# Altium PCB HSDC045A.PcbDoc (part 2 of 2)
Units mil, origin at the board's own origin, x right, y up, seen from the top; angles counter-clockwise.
Board outline 3400 x 2200 mil, 4 copper layers (Top Layer, GND, Power, Bottom Layer), stack 60.6 mil thick; 158 components, 100 nets, 469 pads, 343 vias.
Unrouted connection lines stored in the file: 20.
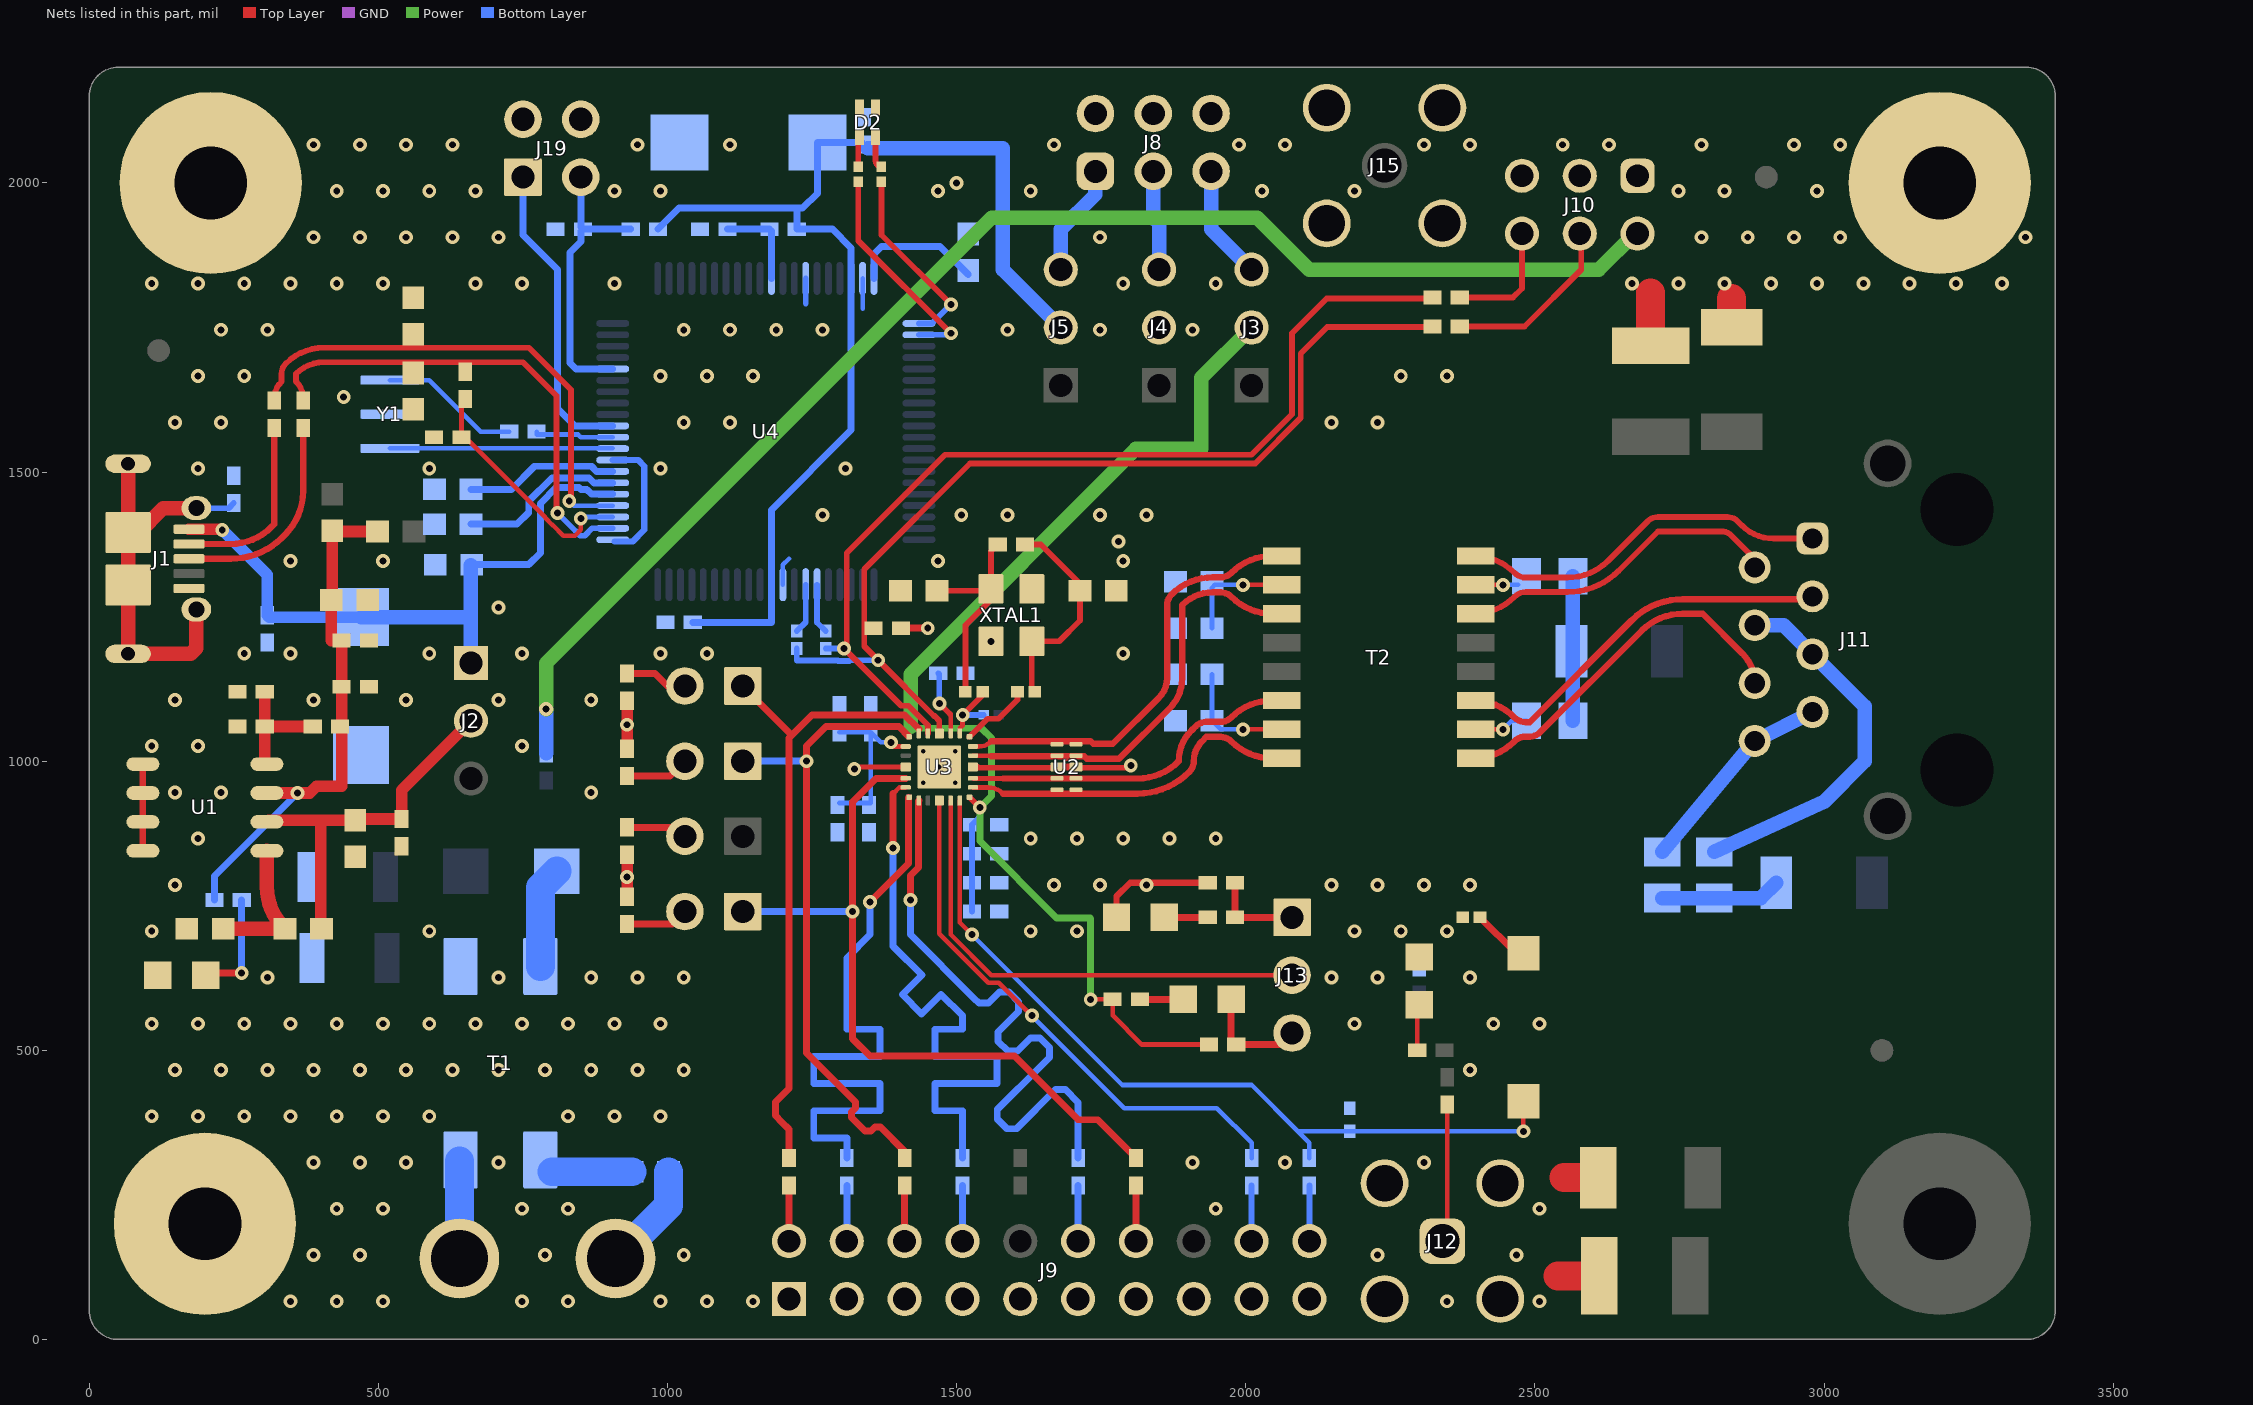
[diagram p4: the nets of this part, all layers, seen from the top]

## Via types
v1: diameter 24, hole 12, Top Layer to Bottom Layer, tented both sides, 337 vias
v2: diameter 19.68, hole 7.87, Top Layer to Bottom Layer, 5 vias
v3: diameter 24, hole 12, Top Layer to Bottom Layer, tented bottom, 1 vias

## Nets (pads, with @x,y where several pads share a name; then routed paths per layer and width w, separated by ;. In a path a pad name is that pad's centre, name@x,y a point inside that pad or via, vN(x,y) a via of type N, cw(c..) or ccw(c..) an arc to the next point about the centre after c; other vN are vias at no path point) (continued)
GND: C1.2 C2.1 C3.2 C4.2 C5.2 C6.2 C7.2 C8.2 C9.2 C10.2 C11.2 C12.2 C13.2 C14.2 C15.2 C16.2 C17.2 C18.2 C19.2 C20.2 C21.2 C22.2 C23.1 C26.2 C27.1 C28.1 C29.2 C30.1 C31.2 C32.2 C33.1 C34.2 C35.2 C36.1 C37.1 C38.1 C39.1 C40.1 D2.3 D2.4 H1.1 H2.1 H3.1 J1.5 J8.2 J8.4 J8.6 J9.1 J9.3 J9.5 J9.7 J9.9 J9.11 J9.13 J9.15 J9.17 J9.19 J10.1 J10.3 J10.5 J12.2 J12.3 J12.4 J12.5 J15.2 J15.3 J15.4 J15.5 J19.2 J19.4 LD1.2 LD3.2 LD4.2 R5.1 R6.1 R7.2 R21.2 R22.1 R31.1 R34.2 R35.2 R36.2 R51.2 T1.3 U1.5 U1.6 U1.7 U1.8 U2.3@1673.56,990 U2.8@1706.44,990 U3.9 U3.21 U3.25 U4.14 U4.19 U4.49 U4.61 U4.68 XTAL1.2 XTAL1.4 Y1.2 | length 1383.2
  Top Layer w8: v1(1322.98,986.69) 1319.73,986.69 1316.42,990 U3.21@1411.93,990
  Top Layer w10: U3.9@1528.07,990 1536.58,990 1538.08,988.5 1673.56,988.5 U2.3@1673.56,989.76 ; U2.8@1706.44,990 1706.44,988.5 1798.5,988.5 1801.09,991.09 v1(1801.09,992.5)
  Top Layer w11: U1.8@92.72,845 U1.7@92.72,895 U1.6@92.72,945 U1.5@92.72,995 ; LD4.2@1776.38,730 1776.38,766.38 1800,790 R31.1@1934.09,790
  Top Layer w12: U2.3@1673.56,990 1673.56,989.76 1706.19,989.76 U2.8@1706.44,990
  Top Layer w50: 2540,110 C27.1@2611.26,110 ; 2550,280 R35.2@2609.45,280 ; C28.1@2700,1718.74 2700,1810 ; R34.2@2840,1750.55 2840,1800
  GND w10: v1@1800,991.41 v1(1801.09,992.5)
  Bottom Layer w8: U4.49@1199.53,1305.24 1199.53,1339.53 1210,1350 ; 1337.32,1782.68 U4.19@1337.32,1834.76
  Bottom Layer w10: 1238.9,1791.57 U4.14@1238.9,1834.76
  Bottom Layer w11: U4.68@905.24,1520.79 949.21,1520.79 960,1510 960,1400 940,1380 U4.61@908.23,1380
  other v1: 348,66 428,66 508,66 748,66 828,66 988,66 1068,66 1148,66 2348,66 2508,66 388,146 468,146 788,146 1028,146 2228,146 2468,146 428,226 508,226 748,226 828,226 1948,226 2508,226 388,306 468,306 548,306 708,306 1908,306 2068,306 2308,306 108,386 188,386 268,386 348,386 428,386 508,386 588,386 828,386 908,386 988,386 148,466 228,466 308,466 388,466 468,466 548,466 628,466 708,466 788,466 868,466 948,466 1028,466 2388,466 108,546 188,546 268,546 348,546 428,546 508,546 588,546 668,546 748,546 828,546 908,546 988,546 2188,546 2428,546 2508,546 308,626 708,626 868,626 948,626 1028,626 2148,626 2228,626 2388,626 108,706 588,706 1628,706 1708,706 2188,706 2268,706 2348,706 148,786 1668,786 1748,786 1828,786 2148,786 2228,786 2308,786 2388,786 188,866 1628,866 1708,866 1788,866 1868,866 1948,866 148,946 228,946 868,946 108,1026 188,1026 748,1026 148,1106 388,1106 548,1106 708,1106 868,1106 268,1186 348,1186 588,1186 748,1186 988,1186 1068,1186 1788,1186 1559.13,1207.31 708,1266 348,1346 508,1346 1468,1346 1788,1346 1780,1380 1268,1426 1508,1426 1588,1426 1748,1426 1828,1426 188,1506 588,1506 988,1506 1308,1506 148,1586 228,1586 1028,1586 1108,1586 2148,1586 2228,1586 440,1630 188,1666 268,1666 988,1666 1068,1666 1148,1666 2268,1666 2348,1666 228,1746 308,1746 1028,1746 1108,1746 1188,1746 1268,1746 1588,1746 1748,1746 1908,1746 108,1826 188,1826 268,1826 348,1826 428,1826 508,1826 668,1826 748,1826 908,1826 1788,1826 1948,1826 2668,1826 2748,1826 2828,1826 2908,1826 2988,1826 3068,1826 3148,1826 3228,1826 3308,1826 388,1906 468,1906 548,1906 628,1906 708,1906 1748,1906 2788,1906 2868,1906 2948,1906 3028,1906 3348,1906 428,1986 508,1986 588,1986 668,1986 908,1986 988,1986 1468,1986 1628,1986 2028,1986 2188,1986 2748,1986 2828,1986 2988,1986 1500,2000 388,2066 468,2066 548,2066 628,2066 948,2066 1108,2066 1668,2066 1988,2066 2068,2066 2308,2066 2388,2066 2548,2066 2628,2066 2788,2066 2948,2066 3028,2066
  other v2: 1442.44,962.44 1497.56,962.44 1470,990 1442.44,1017.56 1497.56,1017.56
LED_0: J13.2 U3.4 | length 851.1
  Top Layer w8: U3.4@1489.69,931.93 1489.69,700.31 1560,630 J13.2@2080,630
MCU_VCC: C35.1 C36.2 C37.2 J5.2 R49.1 R52.1 U4.18 U4.50 | length 2032.6
  Bottom Layer w12: R49.1@983.62,1920 1020,1956.38 1233.62,1956.38 1259.09,1981.85 C35.1@1259.09,2070 C36.2@1336.38,2070 ; C37.2@1043.62,1240 1043.78,1240.16 1179.84,1240.16 U4.50@1179.84,1305.24 1179.84,1434.57 1317.64,1572.36 U4.18@1317.64,1834.76 1317.64,1887.64 1285.28,1920 R52.1@1223.62,1920 1223.62,1952.76
  Bottom Layer w25: C36.2@1346.38,2060 1580,2060 1580,1850 J5.2@1680,1750
MCU_VCC_EXT: J5.3 J8.1 | length 194.9
  Bottom Layer w25: J5.3@1680,1850 1680,1920 1740,1980 J8.1@1740,2020
MDC: R18.1 R46.1 U3.16 | length 1686.8
  Top Layer w10: v1(1304.96,1195.04) v1(1304.96,1195.04) ; U3.16@1450.31,1048.07 1450.57,1048.32 1450.57,1062.06 1416.63,1096 1404,1096 1310,1190 1310,1360 1480,1530 2010,1530 2080,1600 2080,1740 2140,1800 2320.79,1800 R18.1@2322.6,1801.81
  Bottom Layer w10: R46.1@1273.5,1195.04 v1(1304.96,1195.04)
MDC_EXT: J10.6 R18.2 | length 209
  Top Layer w10: R18.2@2369.84,1801.81 2461.81,1801.81 2477.5,1817.5 J10.6@2477.5,1912.31
MDC_OB: R46.2 U4.46 | length 86.5
  Bottom Layer w10: U4.46@1258.58,1305.24 1258.58,1239.88 R46.2@1273.5,1224.96
MDIO: R19.1 R20.1 R47.1 U3.15 | length 1722.5
  Top Layer w10: U3.15@1470,1048.07 1470,1070 1462,1078 1460.89,1078 v1(1364.32,1174.57) 1340,1198.89 1340,1331.73 1523.27,1515 2016.21,1515 2095,1593.79 2095,1705 2140.81,1750.81 2321.6,1750.81 R19.1@2322.6,1751.81
  Bottom Layer w10: R47.1@1223.5,1195.04 1223.5,1174.57 1224.06,1174.02 1294.32,1174.02 1295.3,1173.04 1314.07,1173.04 1315.6,1174.57 v1(1364.32,1174.57)
MDIO_EXT: J10.4 R19.2 | length 314.2
  Top Layer w10: R19.2@2369.84,1751.81 2481.81,1751.81 2580,1850 2580,1909.81 J10.4@2577.5,1912.31
MDIO_OB: R47.2 U4.47 | length 86.7
  Bottom Layer w10: R47.2@1223.5,1224.96 1238.9,1240.35 U4.47@1238.9,1305.24
MSP_XIN2: U4.69 Y1.3 | length 384.8
  Bottom Layer w8: Y1.3@520,1540.94 U4.69@904.76,1540.94
MSP_XOUT2: R48.2 U4.70 | length 138.8
  Bottom Layer w8: R48.2@773.62,1570 773.62,1564.84 845.16,1564.84 850,1560 905.08,1560 U4.70@905.24,1560.16
NetC3_1: C3.1 C4.1 J2.2 R2.2 U1.2 | length 638.9
  Top Layer w20: U1.2@310.16,897.87 400,897.87 ; R2.2@401.5,710 400,711.5 400,897.87 ; J2.2@660,1070 540,950 C3.1@540,900 462.13,900 C4.1@460,897.87 400,897.87
NetC5_1: C5.1 C6.1 C7.1 L1.1 R1.1 R3.2 R4.2 U1.3 | length 898.7
  Top Layer w20: U1.3@307.28,945 v1(360,945) 381.18,945 392.95,956.77 436.38,956.77 C5.1@436.38,1128.7 C6.1@436.38,1208.7 ; 418.5,1208.7 C7.1@418.5,1278.7 ; C7.1@420,1278.7 L1.1@420,1397.22 ; L1.1@420,1398.5 L1.1@420,1397.22 ; R1.1@498.5,1397.22 L1.1@420,1397.22
  Bottom Layer w12: R4.2@216.38,760 216.38,801.38 v1(360,945)
NetC8_1: C8.1 R3.1 R6.2 U1.4 | length 209.3
  Top Layer w20: C8.1@303.62,1120 R6.2@303.62,1060 ; U1.4@307.28,995 303.62,998.66 R6.2@303.62,1060 ; R3.1@386.38,1060 R6.2@303.62,1060
NetC11_1: C11.1 C12.1 T2.2 | length 177.8
  Top Layer w8: v1(1995,1305) T2.2@2047.36,1305
  Bottom Layer w8: C11.1@1941.5,1230.06 1941.5,1299.91 1946.58,1305 v1(1995,1305)
NetC21_1: C21.1 C22.1 T2.7 | length 192.1
  Top Layer w8: v1(1995,1055) T2.7@2047.36,1055
  Bottom Layer w8: C22.1@1941.5,1150.03 C21.1@1941.5,1070 1956.5,1055 v1(1995,1055)
NetC24_1: C24.1 R23.1 R24.1 | length 250
  Bottom Layer w25: R23.1@2565.59,1070 R24.1@2565.59,1320
NetC25_1: C25.1 R25.1 R26.1 | length 208.4
  Bottom Layer w25: R26.1@2720,763.31 R25.1@2810,763.31 2890.63,763.31 C25.1@2917.32,790
NetC26_1: C26.1 R33.1 R37.2 XTAL1.3 | length 367.1
  Top Layer w10: R37.2@1618.19,1374.72 1645.28,1374.72 1713.07,1306.93 C26.1@1713.07,1294.66 1713.07,1243.07 1677.31,1207.31 XTAL1.3@1630,1207.31 R33.1@1630,1124.96
NetC29_1: C29.1 R37.1 R38.1 XTAL1.1 | length 349
  Top Layer w10: C29.1@1466.06,1294.72 XTAL1.1@1555.99,1294.72 ; R38.1@1515.04,1120 1515.04,1234.96 XTAL1.1@1559.13,1279.05 ; XTAL1.1@1559.13,1297.87 1559.13,1362.91 R37.1@1570.94,1374.72
NetC31_1: C31.1 U4.67 | length 265.5
  Bottom Layer w12: C31.1@660,1470 730,1470 770,1510 868.4,1510 877.3,1501.1 U4.67@905.24,1501.1
NetC32_1: C32.1 U4.20 | length 230.7
  Bottom Layer w12: U4.20@1357.01,1834.76 1357.01,1877.01 1370,1890 1471.5,1890 C32.1@1520,1841.5
NetC34_1: C34.1 U4.66 | length 293.7
  Bottom Layer w12: C34.1@660,1410 740,1410 760,1430 760,1450.04 799.96,1490 864.36,1490 872.94,1481.42 U4.66@905.24,1481.42
NetC38_2: C38.2 R52.2 U4.11 | length 154.5
  Bottom Layer w12: C38.2@1103.62,1920 R52.2@1176.38,1920 ; U4.11@1179.84,1834.76 R52.2@1179.84,1916.54
NetD1_2: D1.2 T1.4 | length 176.8
  Bottom Layer w50: T1.4@780,645.13 780,781.26 D1.2@808.74,810
NetD2_1: D2.1 R45.1 | length 48.8
  Top Layer w10: R45.1@1329.84,2028.3 D2.1@1329.84,2077.12
NetD2_2: D2.2 R44.1 | length 57
  Top Layer w10: D2.2@1359.84,2079.56 1359.84,2038.3 ccw(c1369.84,2038.3) R44.1@1369.84,2028.3
NetF1_1: F1.1 J6.1 | length 187.9
  Bottom Layer w50: J6.1@910,140 1001.5,231.5 F1.1@1001.5,290
NetF1_2: F1.2 T1.1 | length 138
  Bottom Layer w50: T1.1@800.49,290 F1.2@938.5,290
NetJ1_6: J1.6 J1.7 J1.8 J1.9 J1.10 J1.11 R7.1 | length 722.1
  Top Layer w25: J1.10@67.09,1514.37 J1.9@67.09,1395.28 ; J1.6@185.2,1262.4 185.2,1195.2 175.63,1185.63 J1.7@67.09,1185.63 J1.8@67.09,1304.72 J1.9@67.09,1395.28 ; J1.11@185.2,1437.6 127.6,1437.6 85.28,1395.28 J1.9@67.09,1395.28
  Bottom Layer w10: J1.11@185.2,1437.6 241.22,1437.6 R7.1@250,1446.38
NetJ7_1: J7.1 T1.2 | length 158.3
  Bottom Layer w50: J7.1@640,150 T1.2@640,308.27
NetJ11_4: J11.4 J11.5 R25.2 | length 650.8
  Bottom Layer w25: R25.2@2810,843.31 3000,930 3070,1000 3070,1095 J11.5@2980,1185 2930,1235 J11.4@2880,1235
NetJ11_7: J11.7 J11.8 R26.2 | length 361.5
  Bottom Layer w25: R26.2@2720,843.31 J11.8@2880,1035 J11.7@2980,1085
NetJ12_1: J12.1 R27.2 | length 239.8
  Top Layer w8: J12.1@2340,170 2348.19,178.19 R27.2@2348.19,406.38
NetJ13_1: J13.1 R31.2 R32.1 | length 158.7
  Top Layer w12: R31.2@1981.34,790 R32.1@1981.34,730 J13.1@2080,730
NetJ13_3: J13.3 LD2.2 R29.1 | length 186.6
  Top Layer w12: LD2.2@1974.67,588.22 1974.67,518.96 R29.1@1983.62,510 2060,510 J13.3@2080,530
NetJ14_2: J14.2 R39.1 | length 109
  Top Layer w12: R39.1@930,718.38 1008.38,718.38 J14.2@1030,740
NetJ16_2: J16.2 R40.1 | length 109
  Top Layer w12: R40.1@930,1151.62 978.38,1151.62 1000,1130 J16.2@1030,1130
NetJ17_2: J17.2 R42.1 | length 110.6
  Top Layer w12: R42.1@930,974.38 1004.38,974.38 J17.2@1030,1000
NetJ18_2: J18.2 R43.1 | length 106.5
  Top Layer w12: R43.1@930,885.62 1014.38,885.62 J18.2@1030,870
NetLD1_1: LD1.1 R4.1 | length 190.2
  Top Layer w12: LD1.1@201.34,630 204.96,633.62 v1(263.62,633.62)
  Bottom Layer w12: v1(263.62,633.62) R4.1@263.62,760
NetLD2_1: LD2.1 R28.1 | length 75
  Top Layer w12: R28.1@1816.95,588.22 LD2.1@1891.99,588.22
NetLD3_1: LD3.1 R30.2 | length 79.6
  Top Layer w8: R30.2@2296.38,500 2296.38,569.92 cw(c2308.74,569.92) LD3.1@2300,578.66
NetLD4_1: LD4.1 R32.2 | length 75
  Top Layer w12: LD4.1@1859.06,730 R32.2@1934.09,730
NetR2_1: R2.1 R5.2 U1.1 | length 250.6
  Top Layer w25: R5.2@231.5,710 R2.1@338.5,710 336.57,711.93 cw(c407.28,782.64) 307.28,782.64 U1.1@307.28,845
NetR22_2: R22.2 S1.1 | length 87.7
  Top Layer w12: R22.2@2404.96,730 S1.1@2467.01,667.95
NetR23_2: R23.2 T2.10 | length 99.2
  Top Layer w8: T2.10@2392.64,1055 v1(2445,1055)
  Bottom Layer w8: v1(2445,1055) 2460,1070 R23.2@2485.59,1070
NetR24_2: R24.2 T2.15 | length 78
  Top Layer w8: T2.15@2392.64,1305 v1(2445,1305)
  Bottom Layer w8: v1(2445,1305) R24.2@2470.59,1305
NetR48_1: R48.1 Y1.1 | length 243.3
  Bottom Layer w8: Y1.1@520,1659.06 587.6,1659.06 676.65,1570 R48.1@726.38,1570
P1.0: R44.2 U4.21 | length 331
  Top Layer w10: R44.2@1369.84,2002.31 1369.84,1910.16 v1(1490,1790)
  Bottom Layer w10: U4.21@1434.76,1757.01 1457.01,1757.01 v1(1490,1790)
P1.1: R45.2 U4.22 | length 385
  Top Layer w10: R45.2@1329.84,2002.31 1329.84,1900.16 v1(1490,1740)
  Bottom Layer w10: U4.22@1434.76,1737.32 1487.32,1737.32 v1(1490,1740)
PWDN: R16.2 U3.3 | length 946.5
  Top Layer w8: U3.3@1470,931.93 1470,701.62 1554.62,617 1573,617 v1(1630,560)
  Bottom Layer w8: v1(1630,560) 1790,400 1950,400 2010,340 R16.2@2010,313.62
PWDN_S: J9.18 R16.1 | length 96.4
  Bottom Layer w10: J9.18@2010,170 R16.1@2010,266.38
RBIAS: R21.1 U3.14 | length 111.5
  Top Layer w8: 1489.44,1080.56 1489.44,1048.31 U3.14@1489.69,1048.07
  Top Layer w10: v1(1470,1100) 1488.44,1081.56
  Bottom Layer w10: R21.1@1468.19,1152.13 1470,1150.32 v1(1470,1100)
RD_N: T2.8 U2.5 U2.6 U3.7 | length 582.2
  Top Layer w8: U3.7@1528.07,954.57 1554.49,954.57 cw(c1554.49,918.49) 1580,944
  Top Layer w11: 1580,944 1812.58,944 ccw(c1812.58,1070) 1901.67,980.9 1902.38,981.62 ccw(c1884,1000) 1910,1000 cw(c1959.07,1000) 1924.37,1034.7 1931.67,1042 1956.36,1042 cw(c1956.36,1015.67) 1974.97,1034.29 ccw(c2045.69,1105) 2045.69,1005 T2.8@2047.36,1005
RD_P: T2.6 U2.4 U2.7 U3.8 | length 579
  Top Layer w8: U3.8@1528.39,970 1580,970
  Top Layer w11: 1580,970 1812.58,970 ccw(c1812.58,1070) 1883.29,999.29 1884,1000 cw(c1959.07,1000) 1905.99,1053.08 1913.29,1060.38 cw(c1931.67,1042) 1931.67,1068 1956.36,1068 ccw(c1956.36,1094.33) 1974.97,1075.71 cw(c2045.69,1005) 2045.69,1105 T2.6@2047.36,1105
RESET: C23.2 R17.2 S1.2 U3.5 | length 1441.7
  Top Layer w8: U3.5@1505.43,931.93 1505.43,721.09 v1(1526.53,700) ; v1(2480,360) S1.2@2480,412.05
  Bottom Layer w8: v1(1526.53,700) 1786.53,440 2010,440 2090,360 ; R17.2@2110,313.62 2110,340 2090,360 ; v1(2480,360) 2090,360
RESET_S: J9.20 R17.1 | length 96.4
  Bottom Layer w10: J9.20@2110,170 R17.1@2110,266.38
RST/SBWTDIO: C30.2 J19.3 R49.2 U4.76 | length 487.6
  Bottom Layer w12: C30.2@850,1923.62 J19.3@850,2010 ; U4.76@905.24,1678.27 841.73,1678.27 831.65,1688.35 831.65,1880 850,1898.35 850,1916.38 C30.2@853.62,1920 R49.2@936.38,1920
RX_D0: J17.1 R11.2 U3.18 | length 1121.6
  Top Layer w12: R11.2@1410,313.62 1410,325.5 1368.37,367.13 1358.4,367.13 1351.6,360.34 1341.63,360.34 1318.37,383.6 1318.37,393.57 1325.16,400.37 1325.16,410.34 1240,495.5 v1(1240,1000) 1240,1025.98 1274.02,1060 1400,1060 U3.18@1416.85,1043.15
  Bottom Layer w12: J17.1@1130,1000 v1(1240,1000)
RX_D0_S: J9.6 R11.1 | length 96.4
  Top Layer w12: J9.6@1410,170 R11.1@1410,266.38
RX_D1: J16.1 R9.2 U3.17 | length 1110.3
  Top Layer w12: J16.1@1130,1130 1210,1050 ; R9.2@1210,313.62 1210,351.75 1210,363.5 1198.25,375.25 1186.5,387 1186.5,410.5 1198.25,422.25 1210,434 1210,950 1210,1040 1250,1080 1410,1080 U3.17@1434.57,1055.43
RX_D1_S: J9.2 R9.1 | length 96.4
  Top Layer w12: J9.2@1210,170 R9.1@1210,266.38
RX_ER: J14.1 R15.2 U3.22 | length 1283.8
  Top Layer w12: U3.22@1411.93,970.31 1360.78,970.31 1320,929.54 v1(1320,740) 1320,520 1350,490 1600,490 1710,380 1743.62,380 R15.2@1810,313.62
  Bottom Layer w12: J14.1@1130,740 v1(1320,740)
RX_ER_S: J9.14 R15.1 | length 96.4
  Top Layer w12: J9.14@1810,170 R15.1@1810,266.38
TARGET_D_N: C40.2 R53.1 U4.64 | length 867.8
  Top Layer w10: R53.1@320,1623.62 320,1626.69 cw(c362.68,1626.69) 332.5,1656.87 332.5,1670 cw(c357.5,1670) 339.82,1687.68 cw(c405.78,1621.72) 405.78,1715 760.36,1715 833,1642.36 v1@833,1453
  Bottom Layer w8: v1(830,1450) 837.95,1442.05 U4.64@905.24,1442.05
TARGET_D_P: C39.2 R50.2 R54.1 U4.62 | length 853.2
  Top Layer w10: R54.1@370,1623.62 370,1626.69 ccw(c327.32,1626.69) 357.5,1656.87 357.5,1670 cw(c405.78,1621.72) 405.78,1690 750,1690 808,1632 808,1430.99 v1(809.49,1429.49)
  Bottom Layer w10: v1(809.49,1429.49) 809.49,1429.39 840.89,1398 840.99,1398 848.99,1390 856.85,1390 869.53,1402.68 U4.62@905.24,1402.68
  Bottom Layer w11: v1(809.49,1429.49) v1@811.65,1427.34
TARGET_PUR: R50.1 R51.1 U4.63 | length 441.9
  Top Layer w8: R50.1@650,1626.38 643.62,1620 R51.1@643.62,1560 650,1560 788.49,1421.51 788.49,1420.8 800.8,1408.49 801.51,1408.49 820,1390 840,1390 850,1400 v1(850,1420)
  Bottom Layer w8: v1(850,1420) 844.72,1420 842.36,1422.36 U4.63@905.24,1422.36
TD_CH1_N: J11.2 T2.14 | length 567.4
  Top Layer w10: T2.14@2392.64,1255 2393.81,1255 ccw(c2393.81,1355) 2464.53,1284.29 cw(c2484.35,1264.47) 2484.35,1292.5 2556.08,1292.5 ccw(c2556.08,1417.5) 2644.47,1329.11 2712.68,1397.32 2822.32,1397.32 cw(c2822.32,1372.32) 2840,1390 2869.39,1360.61 cw(c2843.79,1335) J11.2@2880,1335
TD_CH1_P: J11.1 T2.16 | length 646.5
  Top Layer w10: T2.16@2392.64,1355 2393.81,1355 cw(c2393.81,1255) 2464.53,1325.71 ccw(c2484.35,1345.53) 2484.35,1317.5 2556.08,1317.5 ccw(c2556.08,1417.5) 2626.79,1346.79 2695,1415 cw(c2712.68,1397.32) 2712.68,1422.32 2832.68,1422.32 cw(c2832.68,1397.32) 2850.36,1415 2857.68,1407.68 ccw(c2912.43,1462.43) 2912.43,1385 J11.1@2980,1385
TD_CH2_N: J11.6 T2.9 | length 644.2
  Top Layer w11: T2.9@2392.64,1005 2393.81,1005 ccw(c2393.81,1105) 2464.53,1034.29 cw(c2484.35,1014.47) 2484.35,1042.5 2491.14,1042.5 ccw(c2491.14,1067.5) 2508.82,1049.82 2684.71,1225.71 cw(c2755.42,1155) 2755.42,1255 2790,1255 2858.79,1186.21 cw(c2807.57,1135) J11.6@2880,1135
TD_CH2_P: J11.3 T2.11 | length 681.4
  Top Layer w11: T2.11@2392.64,1105 2393.81,1105 cw(c2393.81,1005) 2464.53,1075.71 ccw(c2484.35,1095.53) 2484.35,1067.5 2491.14,1067.5 2667.03,1243.39 cw(c2755.42,1155) 2755.42,1280 2967.93,1280 ccw(c2967.93,1297.07) J11.3@2980,1285
TD_N: T2.3 U2.2 U2.9 U3.10 | length 737.8
  Top Layer w8: U3.10@1528.07,1009.69 1556.84,1009.69 cw(c1556.84,1005.21) 1560,1008.37
  Top Layer w11: 1560,1008.37 1687.88,1008.37 1690,1006.26 1692.12,1008.37 1720.76,1008.37 1725.13,1004 1780.77,1004 1868.38,1091.62 ccw(c1816.2,1143.8) 1890,1143.8 1890,1270 cw(c1943.11,1216.89) 1943.11,1292 1956.36,1292 cw(c1956.36,1265.67) 1974.97,1284.29 ccw(c2045.69,1355) 2045.69,1255 T2.3@2047.36,1255
TD_P: T2.1 U2.1 U2.10 U3.11 | length 737
  Top Layer w8: U3.11@1528.07,1025.43 1538.41,1025.43 ccw(c1538.41,1055.96) 1560,1034.37
  Top Layer w11: 1560,1034.37 1731.52,1034.37 1735.9,1030 1770,1030 1850,1110 ccw(c1816.2,1143.8) 1864,1143.8 1864,1270 cw(c1890,1270) 1871.62,1288.38 cw(c1943.11,1216.89) 1943.11,1318 1956.36,1318 ccw(c1956.36,1344.33) 1974.97,1325.71 cw(c2045.69,1255) 2045.69,1355 T2.1@2047.36,1355
TEST/SBWTCK: J19.1 U4.71 | length 532.6
  Bottom Layer w12: J19.1@750,2010 750,1910 810,1850 810,1610 840.16,1579.84 U4.71@905.24,1579.84
TX_D0: R12.2 U3.23 | length 1112.6
  Top Layer w8: 1390,943.82 1400.75,954.57 U3.23@1411.93,954.57
  Top Layer w12: v1(1390,850) 1390,943.82
  Bottom Layer w12: v1(1390,850) 1390,680 1439.85,630.15 1406.1,596.4 1439.33,563.16 1473.09,596.91 1510,560 1510,536.5 1462.27,536.5 1462.27,489.5 1569.97,489.5 1569.97,442.5 1462.27,442.5 1462.27,395.5 1510,395.5 R12.2@1510,313.62
TX_D0_S: J9.8 R12.1 | length 96.4
  Bottom Layer w12: J9.8@1510,170 R12.1@1510,266.38
TX_D1: R10.2 U3.24 | length 1124.8
  Top Layer w12: v1(1350,756.3) 1416.85,823.15 U3.24@1416.85,936.85
  Bottom Layer w12: R10.2@1310,313.62 1310,320 1310,348.5 1252.84,348.5 1252.84,395.5 1310,395.5 1367.16,395.5 1367.16,442.5 1310,442.5 1252.84,442.5 1252.84,489.5 1310,489.5 1367.16,489.5 1367.16,536.5 1310,536.5 1310,560 1310,630 1310,660 1350,700 v1(1350,756.3)
TX_D1_S: J9.4 R10.1 | length 96.4
  Bottom Layer w12: J9.4@1310,170 R10.1@1310,266.38
TX_EN: R14.2 U3.1 | length 1125.1
  Top Layer w12: v1(1420,760) 1420,802.26 1433.85,816.11 1433.85,931.21 U3.1@1434.57,931.93
  Bottom Layer w12: v1(1420,760) 1420,700 1530,590 1538.31,581.69 1554.93,581.69 1573.85,600.62 1590.47,600.62 1607.09,584 1607.09,567.39 1579.85,540.15 1571.76,532.06 1571.76,515.45 1588.38,498.83 1605,498.83 1613.09,506.91 1627.32,521.15 1643.94,521.15 1660.55,504.53 1660.55,487.92 1646.32,473.68 1570.21,397.57 1570.21,380.96 1586.83,364.34 1603.45,364.34 1671.24,432.14 1687.86,432.14 1710,410 R14.2@1710,313.62
TX_EN_S: J9.12 R14.1 | length 96.4
  Bottom Layer w12: J9.12@1710,170 R14.1@1710,266.38
USB_N: J1.2 R53.2 | length 323.9
  Top Layer w11: J1.2@172.4,1375.59 244.17,1375.59 ccw(c244.17,1475.59) 314.88,1404.88 320,1410 R53.2@320,1576.38
USB_P: J1.3 R54.2 | length 371
  Top Layer w11: J1.3@172.4,1350 244.58,1350 ccw(c244.58,1476) 333.67,1386.9 338.38,1391.62 ccw(c262.06,1467.94) 370,1467.94 R54.2@370,1576.38
USB_VBUS: C1.1 C2.2 C33.2 J1.1 J2.1 U4.65 | length 1113.1
  Top Layer w20: J1.1@172.4,1401.18 228.82,1401.18 v1(230,1400)
  Bottom Layer w12: C33.2@661.5,1340 760,1340 780,1360 780,1446 807,1473 847,1473 850,1470 860.32,1470 868.58,1461.73 U4.65@905.24,1461.73
  Bottom Layer w20: v1(230,1400) 307.6,1322.4 C2.2@307.6,1252.44 310.94,1249.09 C1.1@470,1249.09
  Bottom Layer w25: C1.1@470,1249.09 659.09,1249.09 ; J2.1@660,1170 C33.2@660,1338.5
VDDA3P3: C13.1 C14.1 C17.1 C18.1 J3.2 R28.2 R29.2 U3.6 | length 2185.1
  Top Layer w8: v1(1731.78,588.22) R28.2@1769.7,588.22 1769.7,560.3 1820,510 R29.2@1936.38,510
  Top Layer w10: U3.6@1523.15,936.85 v3(1540,920)
  Power w12: 1420.28,1059.72 1423,1057 1543,1057 1560,1040 1560,940 v3(1540,920) 1540,861.65 1672.65,729 1731,729 1731.78,728.22 v1(1731.78,588.22)
  Power w25: 1420.28,1059.72 1420.28,1150.28 1810,1540 1922.94,1540 1922.94,1662.94 J3.2@2010,1750
  Bottom Layer w10: C13.1@1526.38,740 C14.1@1526.38,790 C18.1@1526.38,840 C17.1@1526.38,890 1540,903.62 v3(1540,920)
VDDA3P3_EXT: J3.3 J8.5 | length 199
  Bottom Layer w25: J8.5@1940,2020 1940,1920 J3.3@2010,1850
VDDIO: C15.1 C16.1 C19.1 C20.1 J4.2 R20.2 R39.2 R40.2 R42.2 R43.2 U3.19 | length 512.2
  Top Layer w8: v1(1386.66,1032.68) 1386.66,1025.43 U3.19@1411.93,1025.43
  Top Layer w12: R20.2@1403.62,1230 v1(1450,1230)
  Top Layer w20: R39.2@930,765.62 R43.2@930,838.38 ; R42.2@930,1021.62 R40.2@930,1104.38
  GND w8: v1@1383.44,1035.91 v1(1386.66,1032.68)
  Bottom Layer w8: C15.1@1297.26,927.72 1351.65,927.72 C20.1@1351.65,1050 ; C19.1@1297.26,1050 C20.1@1351.65,1050 ; v1(1386.66,1032.68) 1368.97,1032.68 C20.1@1351.65,1050
  other v1: 930,800 930,1063
VDDIO_EXT: J4.3 J8.3 | length 174.1
  Bottom Layer w25: J8.3@1840,2020 1840,1940 1850,1930 J4.3@1850,1850
VFX: J10.2 R8.1 | length 2425.7
  Power w25: v1(790,1090) 790,1169.73 1560.27,1940 2020,1940 2110,1850 2610,1850 2672.31,1912.31 J10.2@2677.5,1912.31
  Bottom Layer w25: R8.1@790,1013.62 v1(790,1090)
XI: R38.2 R41.2 U3.13 | length 119.4
  Top Layer w8: U3.13@1505.43,1048.07 1505.43,1056.69 1510,1061.26 v1@1510,1079.56
  Top Layer w10: v1@1510,1079.56 v1(1510.44,1080) R38.2@1544.96,1114.52
  Bottom Layer w10: v1(1510.44,1080) R41.2@1547.01,1080
XO: R33.2 U3.12 | length 123.2
  Top Layer w10: U3.12@1522.17,1042.17 1553.5,1073.5 1572.36,1073.5 1605.04,1106.18 R33.2@1605.04,1120
pads on no net: FID1.1 FID2.1 FID3.1 FID4.1 FID5.1 FID6.1 H5.0 H6.0 H7.0 H8.0 J1.4 J9.16 J11. LBL1.0 T2.4 T2.5 T2.12 T2.13 U2.3@1673.56,990 U2.8@1706.44,990 U4.1 U4.2 U4.3 U4.4 U4.5 U4.6 U4.7 U4.8 U4.9 U4.10 U4.12 U4.13 U4.15 U4.16 U4.17 U4.23 U4.24 U4.25 U4.26 U4.27 U4.28 U4.29 U4.30 U4.31 U4.32 U4.33 U4.34 U4.35 U4.36 U4.37 U4.38 U4.39 U4.40 U4.41 U4.42 U4.43 U4.44 U4.45 U4.48 U4.51 U4.52 U4.53 U4.54 U4.55 U4.56 U4.57 U4.58 U4.59 U4.60 U4.72 U4.73 U4.74 U4.75 U4.77 U4.78 U4.79 U4.80

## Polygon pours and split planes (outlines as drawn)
GND on Top Layer "TOP_LAYER_GND_P004" (solid, remove dead copper, pour order 4): 50,2180 3350,2180 3380,2150 3380,1800 2650,1800 2300,1600 2300,1500 2030,1500 2030,820 2430,820 2560,690 2560,20 50,20 20,50 20,2150
EARTH_GND on Top Layer "Top_Earth" (solid, remove dead copper, pour order 11): 3380,1600 2600,1600 2530,1500 2400,1500 2400,900 2730,900 2730,20 3360,20 3380,40
GND on GND "GND_GND_P013" (solid, remove dead copper, pour order 13): 50,2180 3350,2180 3380,2150 3380,1800 2650,1800 2300,1600 2300,1500 2030,1500 2030,820 2430,820 2560,690 2560,20 50,20 20,50 20,2150
EARTH_GND on GND "GND_EARTH_GND" (solid, remove dead copper, pour order 14): 3380,1600 2600,1600 2530,1500 2400,1500 2400,900 2730,900 2730,20 3360,20 3380,40
VDDIO on Power "POWER_VDDIO_P015" (solid, remove dead copper, pour order 15): 50,2180 3350,2180 3380,2150 3380,1800 2650,1800 2300,1600 2300,1500 2030,1500 2030,820 2430,820 2560,690 2560,20 50,20 20,50 20,2150
EARTH_GND on Power "POWER_EARTH_GND_P016" (solid, remove dead copper, pour order 16): 3380,1600 2600,1600 2530,1500 2400,1500 2400,900 2730,900 2730,20 3360,20 3380,40
EARTH_GND on Bottom Layer "BOTTOM_LAYER_EARTH_GND_P017" (solid, remove dead copper, pour order 17): 3380,1600 2600,1600 2530,1500 2400,1500 2400,900 2730,900 2730,20 3360,20 3380,40
GND on Bottom Layer "BOTTOM_LAYER_GND_P018" (solid, remove dead copper, pour order 18): 50,2180 3350,2180 3380,2150 3380,1800 2650,1800 2300,1600 2300,1500 2030,1500 2030,820 2430,820 2560,690 2560,20 50,20 20,50 20,2150

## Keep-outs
Keep-Out Layer:
  lines w10: 10,40 40,10 3360,10 3390,40 3390,2160 3360,2190 40,2190 10,2160 10,40
  text ".Layer_Name" at 577,-858.49 h60

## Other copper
Top Layer:
  pour cut-out: 1200,480 1200,135.47 1870,135.47 1870,440 1860,500 1624.54,506.81 1437.13,694.22 1436.04,732.23 1391.06,774.29 1341.55,735.55 1336.31,724.82
  pour cut-out: 1149.78,1087.15 1194.08,1042.85 1193.69,440.76 1194.91,439.53 1194.91,130 1080,130 1080,1080.02
  pour cut-out: 1172.71,1153.84 1318.9,1158.71 1368.01,1110.36 1368.99,1096.31 1243.76,1095.07 1215,1068.07 1172.71,1110.36
  pour cut-out: 1400,1057 1538.08,1057 1538.08,920 1400,920
  pour cut-out: 1566.18,1058.21 1575.4,1058.21 ccw(c1575.4,1062.18) 1578.21,1059.37 1578.4,1059.37 1618.79,1099.76 1749.76,1099.76 1802.93,1152.93 ccw(c1785.86,1170) 1810,1170 1810,1248.56 cw(c1910,1248.56) 1839.29,1319.27 1902.14,1382.13 cw(c1972.86,1311.42) 1972.86,1411.42 2030,1411.42 2030,872.43 ccw(c1987.58,830.02) 1987.58,890 1520,890
  pour cut-out: 3050,1500 2710,1500 2678.28,1468.28 cw(c2607.57,1538.99) 2607.57,1438.99 2400,1438.99 2400,944.09 ccw(c2409.87,953.95) 2409.87,940 3050,940
  text ".Layer_Name" at 587,-858.49 h60
GND:
  text ".Layer_Name" at 577,-858.49 h60
Power:
  text ".Layer_Name" at 597,-868.49 h60
Bottom Layer:
  pour cut-out: 1390,896.91 1190,720 1190,130 1860,135.47 1860,453.62 1792.44,454.27 1548.85,699.47
  text ".Layer_Name" at 577,-858.49 h60

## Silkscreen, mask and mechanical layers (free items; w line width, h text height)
Top Overlay:
  region: 2630,1200 2630,1500 2530,1500 2530,1200
  text "GND" at 570,2100 h35
  text "GND" at 940,2100 h35
  text "EXT / POWER" at 1460,2050 h40
  text "TST" at 560,2000 h40
  text "RST" at 940,2000 h40
  text "MSP-IO" at 1397.27,1890 h35 r270
  text "VDDIO" at 1467.27,1890 h35 r270
  text "VDD3V3" at 1537.27,1889.73 h35 r270
  text "5V-12V" at 2740,1890 h40
  text "CLK_IN" at 2210,1870 h40 r270
  text "MDC" at 2460,1850 h40 r270
  text "MDIO" at 2550,1850 h40 r270
  text "MSTR/SLV" at 980,1430 h40
  text "PHYADD1" at 980,1360 h40
  text "USB" at 651.65,1350 h40 r270
  text "PHYADD0" at 979.06,1289.05 h40
  text "AMDIX" at 980,1220 h40
  text "5V-12V" at 640,880 h40 r270
  text "LED_1" at 2210,750 h40 r270
  text "'.PRJ_Number'.PCB_Rev-" at 2600,730 h85 r90
  text "RESET" at 2587.01,655.4 h40 r270
  text "LED_0" at 1770,640 h40
  text "LDO ON" at 87.28,537.42 h30
  text "RX_D0" at 1430,370 h40 r90
  text "CRS_DV" at 1650,370 h40 r90
  text "RX_ER" at 1830,360 h40 r90
  text "RX_D1" at 1160,300 h40 r90
  text "GND" at 560,250 h40
  text "5V-12V" at 830,250 h40
  text "TX_D1" at 1320,250 h40 r90
  text "TX_D0" at 1540,250 h40 r90
  text "TX_EN" at 1730.5,250 h40 r90
  text "NC" at 1930,250 h40 r90
  text "PWDN" at 2030,250 h40 r90
  text "RESET" at 2130,250 h40 r90
  text "GND" at 1010,50 h40
  text ".Layer_Name" at 577,-858.49 h60
Bottom Overlay:
  text ".Layer_Name" at 577,-858.49 h60
Top Paste:
  lines w10: 1400,1060 1417.83,1042.17 ; 1522.17,937.83 1531.02,928.98 ; 1522.17,1042.17 1537.83,1057.83
  lines w12: 1417.83,920.98 1417.83,937.83
  text ".Layer_Name" at 577,-858.49 h60
Bottom Paste:
  text ".Layer_Name" at 577,-858.49 h60
Top Solder:
  lines w10: 1522.17,937.83 1531.02,928.98 ; 1522.17,1042.17 1537.83,1057.83
  lines w12: 1400,1060 1417.83,1042.17 ; 1416.85,920 1416.85,936.85
  text ".Layer_Name" at 577,-858.49 h60
  text ".Layer_Name" at 577,-858.49 h60
Bottom Solder:
  text ".Layer_Name" at 577,-858.49 h60
Drill Guide:
  text ".Layer_Name" at 577,-858.49 h60
M1 Board Outline:
  text ".Layer_Name" at 577,-858.49 h60
M2 Board Dimensions:
  rectangle: 0,-275 125,-150
  rectangle: 125,-400 500,-275
  lines w7: 0,-275 1000,-275 ; 125,-400 125,-150 ; 250,-400 250,-150 ; 500,-400 500,-150 ; 750,-400 750,-150 ; 0,-400 1000,-400 1000,-150 0,-150 0,-400
  text ".Layer_Name" at 577,-858.49 h60
M3 3D STEP Top:
  text ".Layer_Name" at 577,-858.49 h60
M4 3D STEP Bottom:
  text ".Layer_Name" at 577,-858.49 h60
M5 Assembly Top:
  lines w10: -292,-930.17 6308,-930.17 ; -292,-726.83 6310,-726.83 ; -292,-523.5 -292,-1133.5 3713,-1133.5 6310,-1133.5 6310,-523.5 -291.5,-523.5 -291.5,-1133.5 1284,-1133.5 ; 2173,-1133.5 2173,-523.5 ; 3440,-726.83 3440,-523.5 ; 4280,-726.83 4280,-523.5 ; 4902,-1140 4902,-937.17
  text "COMPONENTS MARKED 'DNP' SHOULD NOT BE POPULATED." at 1153.5,-318.5 h60
  text "ASSEMBLY VARIANT:" at 1153,-434 h60
  text ".VariantName" at 2189,-434 h60
  text "PCB VIEWED FROM TOP SIDE" at -228.5,-655.67 h60
  text "BOARD #:" at 2248,-655.67 h60
  text ".PRJ_Number" at 2793.5,-655.67 h60
  text "REV:" at 3638,-655.67 h60
  text ".PCB_Rev" at 3929.5,-655.67 h60
  text "SVN REV:" at 4476,-655.67 h60
  text ".VersionControl_RevNumber" at 4982,-655.67 h60
  text "TID #:" at 2248,-859 h60
  text ".TID" at 2793.5,-859 h60
  text "PLOT NAME =" at -228.5,-1064.34 h60
  text ".plot_File_Name" at 577,-1064.34 h60
  text "GENERATED    :" at 2250,-1064.34 h60
  text ".Print_Date" at 3119.5,-1064.34 h60
  text ".Print_Time" at 3848.5,-1064.34 h60
  text "TEXAS INSTRUMENTS" at 5113,-1064.34 h60
M6 Assembly Bottom:
  lines w10: -292.5,-727.33 6309.5,-727.33 ; -290.5,-930.67 6309.5,-930.67 ; 1115.5,-1140.5 1115.5,-937.67 ; 1737.5,-727.33 1737.5,-524 ; 2577.5,-727.33 2577.5,-524 ; 3844.5,-1134 3844.5,-524 ; 4733.5,-1134 6309,-1134 6309,-524 -292.5,-524 -292.5,-1134 2304.5,-1134 6309.5,-1134 6309.5,-524
  text "COMPONENTS MARKED 'DNP' SHOULD NOT BE POPULATED." at 6102,-318 h60
  text ".VariantName" at 5058,-434 h60
  text "ASSEMBLY VARIANT:" at 6097,-434 h60
  text ".VersionControl_RevNumber" at 1035.5,-656.17 h60
  text "SVN REV:" at 1541.5,-656.17 h60
  text ".PCB_Rev" at 2088,-656.17 h60
  text "REV:" at 2379.5,-656.17 h60
  text ".PRJ_Number" at 3224,-656.17 h60
  text "BOARD #:" at 3769.5,-656.17 h60
  text "PCB VIEWED FROM BOTTOM SIDE" at 6246,-656.17 h60
  text ".TID" at 3224,-859.5 h60
  text "TID #:" at 3769.5,-859.5 h60
  text "TEXAS INSTRUMENTS" at 904.5,-1064.84 h60
  text ".Print_Time" at 2169,-1064.84 h60
  text ".Print_Date" at 2898,-1064.84 h60
  text "GENERATED    :" at 3767.5,-1064.84 h60
  text ".plot_File_Name" at 5440.5,-1064.84 h60
  text "PLOT NAME =" at 6246,-1064.84 h60
M9 Title Sheet:
  drawing of 57 lines, arcs and shapes, not listed
  text "1" at 739.84,8036.5 h70
  text "2" at 3235.5,8036.5 h70
  text "3" at 5724.84,8036.5 h70
  text "4" at 8231.51,8036.5 h70
  text "5" at 10730.5,8036.5 h70
  text "6" at 13235.5,8036.5 h70
  text "A" at -416.5,6893.5 h70
  text "A" at 14383.5,6893.5 h70
  text "B" at -416.5,4513.5 h70
  text "B" at 14383.5,4513.5 h70
  text "C" at -416.5,2138.5 h70
  text "C" at 14383.5,2138.5 h70
  text "PROJECT TITLE:" at 11343.5,277.5 h45
  text ".PRJ_Title" at 11393.5,144.17 h70
  text "DESIGNED FOR:" at 11343.5,-23.5 h45
  text ".PRJ_Customer" at 11393.5,-163.5 h70
  text "D" at -416.5,-231.5 h70
  text "D" at 14383.5,-231.5 h70
  text "FILE NAME:" at 11343.5,-323.5 h45
  text ".PCB_File_Name_No_Path" at 11393.5,-443.5 h70
  text "Texas Instruments (TI) and/or its licensors do not warrant the accuracy or completeness of this specification" at 6374,-605.34 h45
  text "ENGINEER:" at 11343.5,-613.5 h45
  text "LAYOUT BY:" at 12848.5,-613.5 h45
  text "or any information contained therein. TI and/or its licensors do not warrant that this design will meet" at 6329.01,-718 h45
  text ".PRJ_Engineer" at 11393.5,-768.49 h70
  text ".PCB_Layout" at 12899,-768.49 h70
  text "the specifications, will be suitable for your application or fit for any particular purpose, or will operate in" at 6329.01,-830.67 h45
  text ".Layer_Name" at 577,-858.49 h60
  text "ALTIUM DESIGNER VERSION:" at 12848.5,-923.5 h45
  text "an implementation. TI and/or its licensors do not warrant that the design is production worthy. You should" at 6329.01,-943.33 h45
  text "completely validate and test your design implementation to confirm the system functionality for your application." at 6374,-1056 h45
  text ".print_Scale" at 11393.5,-1056.83 h70
  text ".Application_BuildNumber" at 12899,-1056.83 h70
  text "1" at 739.84,-1263.5 h70
  text "2" at 3235.5,-1263.5 h70
  text "3" at 5724.84,-1263.5 h70
  text "4" at 8231.51,-1263.5 h70
  text "5" at 10730.5,-1263.5 h70
  text "6" at 13235.5,-1263.5 h70
M10 Fab Notes:
  drawing of 189 lines, arcs and shapes, not listed
  text "DESIGN INFORMATION" at 12382.02,6356.17 h60
  text "MIN. TRACK WIDTH:" at 11737.46,6224.05 h60
  text "8" at 12833.7,6224.05 h60
  text "MIL" at 12988.46,6224.05 h60
  text "MIN. CLEARANCE:" at 11737.46,6099.92 h60
  text "0.2" at 12773.7,6099.93 h60
  text "mm" at 12988.46,6099.92 h60
  text "MIN. VIA PAD SIZE:" at 11737.46,5975.8 h60
  text "24" at 12803.71,5975.8 h60
  text "MIL" at 12988.46,5975.8 h60
  text "0.05mm (2MIL)" at 12432.46,5845.9 h60
  text "MINIMUM ANNULAR RING" at 11408.23,5837.67 h60
  text "EXTERNAL" at 13140.46,5837.67 h60
  text "PER" at 11608.23,5727.55 h60
  text "IPC-D-275 CLASS 2 LEVEL C" at 11828.23,5727.54 h60
  text "MIL, HOLES" at 13316.46,5627.07 h60
  text "+/-" at 12924,5618.48 h60
  text "+/-" at 13778,5618.48 h60
  text "REGISTRATION TOLERANCES:" at 11408.23,5617.42 h60
  text "METAL" at 12608,5617.42 h60
  text "5" at 13184.2,5617.42 h60
  text "3" at 14017.2,5617.42 h60
  text "MIL" at 14133.46,5617.42 h60
  text "HOLE SIZE TOLERANCE (UNLESS OTHERWISE SPECIFIED):" at 11408.23,5519.1 h60
  text "+/-" at 13778,5516.23 h60
  text "3" at 14017.2,5515.17 h60
  text "MIL" at 14133.46,5515.17 h60
  text "MATERIAL:" at 11333.46,5377.52 h60
  text "FR-4 High Tg" at 12319.9,5249 h60
  text "X" at 12175.46,5241.01 h60
  text "FR-408" at 11754.46,5236.49 h60
  text "OTHER" at 13242.46,5236.49 h60
  text "62 MIL (1.6mm) +/-10%" at 12074.56,5093.46 h60
  text "X" at 11954.46,5091.01 h60
  text "THICKNESS:" at 11408.23,5085.24 h60
  text "OTHER" at 13359.46,5085.24 h60
  text "TOLERANCE:" at 11408.23,4946.92 h60
  text "X" at 12256.46,4946.92 h60
  text "ANSI IPC-6012 TYPE 3 CLASS 2" at 12434.48,4946.92 h60
  text "OTHER +/-" at 12434.46,4802.73 h60
  text "BOW & TWIST:" at 11408.23,4657.54 h60
  text "X" at 12256.46,4657.54 h60
  text "ANSI IPC-6012 TYPE 3 CLASS 2" at 12434.48,4657.54 h60
  text "OTHER +/-" at 12434.46,4510.85 h60
  text "DRILLING:" at 11333.46,4380.23 h60
  text "NC_DRILL FILES" at 13094.46,4275.04 h60
  text "REFERENCE:" at 11408.23,4271.1 h60
  text "X" at 12065.46,4271.01 h60
  text "AS SHOWN" at 12243.46,4271.1 h60
  text "X" at 12966.46,4271.1 h60
  text "OTHER" at 13392.46,4128.85 h60
  text "PTH COPPER THICKNESS:" at 11407.91,4125.32 h60
  text "X" at 12547.14,4125.32 h60
  text "20-30 um" at 12675.14,4125.32 h60
  text "BOARD FINISH:" at 11333.46,3977.73 h60
  text "SILKSCREEN:" at 11488.68,3867.6 h60
  text "X" at 12446.46,3867.6 h60
  text "TOP" at 12563.46,3867.6 h60
  text "X" at 12956.46,3867.6 h60
  text "BOTTOM" at 13074.46,3867.6 h60
  text "SILKSCREEN COLOR:" at 11488.68,3712.41 h60
  text "X" at 12445.46,3712.41 h60
  text "WHITE" at 12563.46,3712.41 h60
  text "OTHER" at 13074.46,3712.41 h60
  text "BLACK" at 13660,3580 h72.83
  text "X" at 13160,3570 h60
  text "GREEN" at 12694.46,3568.96 h60
  text "OTHER" at 13312.46,3568.96 h60
  text "SOLDER RESIST COLOR:" at 11488.68,3562.1 h60
  text "X" at 13160,3420 h60
  text "MATTE" at 12694.46,3414.71 h60
  text "SEMI-GLOSS" at 13312,3414.07 h60
  text "IMMERSION GOLD (ENIG)" at 12394.46,3241.94 h60
  text "ENEPIG" at 13732,3234.72 h60
  text "SURFACE FINISH:" at 11333.46,3233.72 h60
  text "X" at 12216.46,3233.72 h60
  text "IMM. TIN/SILVER OR EQUIV" at 11663,3096.4 h60
  text "OTHER" at 13094.46,3092.47 h60
  text "ARRAY/PANEL:" at 11333.46,2937.09 h60
  text "CUT AND TRIM PER M1 BOARD OUTLINE" at 12394.46,2928.87 h60
  text "N.C. ROUTE" at 12394.46,2792.9 h60
  text "X" at 13082.46,2792.9 h60
  text "V. SCORE" at 13260.46,2792.9 h60
  text "CERTIFICATION:" at 11333.46,2663.77 h60
  text "MATERIALS AND WORKMANSHIP FOR ALL PCBS" at 12058.46,2663.77 h60
  text "TO MEET OR EXCEED THE REQUIREMENTS OF:" at 12058.46,2569.71 h60
  text "X" at 11695.97,2441.08 h60
  text "ANSI IPC-A-600F CLASS ->" at 11823.96,2441.08 h60
  text "X" at 13471.97,2441.08 h60
  text "2" at 13581.96,2441.08 h60
  text "1" at 13266.96,2439.58 h60
  text "3" at 13935.96,2439.58 h60
  text "X" at 12507.97,2293.39 h60
  text "RoHS" at 12635.96,2293.39 h60
  text "OTHER" at 13280.36,2293.39 h60
  text "PER ORDER" at 13677.42,2293.39 h60
  text "ALL BOARDS MUST MEET OR EXCEED UL94-V0 REQUIREMENTS." at 11361,2139.57 h60
  text "PCB MUST BEAR THE UL94V-0 UL REGISTERED MATERIAL ID NUMBER" at 11361,2023.5 h60
  text "ADDITIONAL REQUIREMENTS:" at 11333.46,1854.08 h60
  text "MICROSECTION:" at 11408.23,1746.95 h60
  text "YES" at 12313.96,1746.95 h60
  text "REQUIRED" at 13175.46,1602.62 h60
  text "BARE BOARD ELEC. TEST:" at 11408.23,1599.76 h60
  text "NONE" at 12713.96,1599.76 h60
  text "X" at 13057.46,1599.76 h60
  text "PER ORDER" at 13767.46,1599.76 h60
  text "XX MIL VIAS REQUIRE NON-CONDUCTIVE FILL AND PLANARIZE" at 11576.38,1394.82 h59
  text "XX MIL VIAS REQUIRE CONDUCTIVE FILL AND PLANARIZE" at 11584.38,1290.84 h60
  text "OUTER XX MIL TRACES REQUIRE 50 OHM SINGLE-ENDED IMPEDANCE" at 11583.39,1127.46 h58
  text "LAYER 2 & 3 (INNER LAYERS) XX MIL WIDE, XX MIL SPACE / TRACES REQUIRE 100 OHM DIFFERENTIAL IMPEDANCE" at 11575.39,891.74 h60
  text "IMPEDANCE CONTROL / Differential Impedance should be 100ohm (+/-10%) /       All 11mil wide differential traces on Top and Bottom Layer. / Single Ended Impedance should be 50ohm (+/-10%) /      All 12mil wide traces on Top and Bottom Layer." at 5280,410 h75
  text ".Layer_Name" at 577,-858.49 h60
M11 Gerber Information:
  lines w10: -292,-930.17 6308,-930.17 ; -292,-726.83 6310,-726.83 ; -292,-523.5 -292,-1133.5 3713,-1133.5 6310,-1133.5 6310,-523.5 -291.5,-523.5 -291.5,-1133.5 1284,-1133.5 ; 2173,-1133.5 2173,-523.5 ; 3440,-726.83 3440,-523.5 ; 4280,-726.83 4280,-523.5 ; 4902,-1140 4902,-937.17
  text "ALL ARTWORK VIEWED FROM TOP SIDE" at -228.5,-655.67 h60
  text "BOARD #:" at 2248,-655.67 h60
  text ".PRJ_Number" at 2793.5,-655.67 h60
  text "REV:" at 3638,-655.67 h60
  text ".PCB_Rev" at 3929.5,-655.67 h60
  text "SVN REV:" at 4476,-655.67 h60
  text ".VersionControl_RevNumber" at 4982,-655.67 h60
  text "LAYER NAME =" at -228.5,-858.49 h60
  text "TID #:" at 2248,-859 h60
  text ".TID" at 2793.5,-859 h60
  text "PLOT NAME =" at -228.5,-1064.34 h60
  text ".plot_File_Name" at 577,-1064.34 h60
  text "GENERATED    :" at 2250,-1064.34 h60
  text ".Print_Date" at 3119.5,-1064.34 h60
  text ".Print_Time" at 3848.5,-1064.34 h60
  text "TEXAS INSTRUMENTS" at 5113,-1064.34 h60
M12 Stackup:
  drawing of 527 lines, arcs and shapes, not listed
  text "Layer" at 8610.58,7807.5 h60
  text "Name" at 9020.49,7807.5 h60
  text "Material" at 9950.23,7807.5 h60
  text "Thickness" at 10810,7807.5 h60
  text "Constant" at 11459.84,7807.5 h60
  text "Board Layer Stack" at 12029.7,7807.5 h60
  text "Board Layer Stack" at 13149.38,7807.5 h60
  text "1" at 8610.58,7687.5 h60
  text "Top Overlay" at 9020.49,7687.5 h60
  text "2" at 8610.58,7567.5 h60
  text "Top Solder" at 9020.49,7567.5 h60
  text "Solder Resist" at 9950.23,7567.5 h60
  text "0.40mil" at 10810,7567.5 h60
  text "3.5" at 11459.84,7567.5 h60
  text "3" at 8610.58,7447.5 h60
  text "Top Layer" at 9020.49,7447.5 h60
  text "Copper" at 9950.23,7447.5 h60
  text "1.40mil" at 10810,7447.5 h60
  text "4" at 8610.58,7327.5 h60
  text "Dielectric 1" at 9020.49,7327.5 h60
  text "FR-4" at 9950.23,7327.5 h60
  text "8.00mil" at 10810,7327.5 h60
  text "4.6" at 11459.84,7327.5 h60
  text "5" at 8610.58,7207.5 h60
  text "GND" at 9020.49,7207.5 h60
  text "Copper" at 9950.23,7207.5 h60
  text "1.40mil" at 10810,7207.5 h60
  text "6" at 8610.58,7087.5 h60
  text "Dielectric 2" at 9020.49,7087.5 h60
  text "FR-4" at 9950.23,7087.5 h60
  text "39.00mil" at 10810,7087.5 h60
  text "4.6" at 11459.84,7087.5 h60
  text "7" at 8610.58,6967.5 h60
  text "Power" at 9020.49,6967.5 h60
  text "Copper" at 9950.23,6967.5 h60
  text "1.40mil" at 10810,6967.5 h60
  text "8" at 8610.58,6847.5 h60
  text "Dielectric 3" at 9020.49,6847.5 h60
  text "FR-4" at 9950.23,6847.5 h60
  text "8.00mil" at 10810,6847.5 h60
  text "4.6" at 11459.84,6847.5 h60
  text "9" at 8610.58,6727.5 h60
  text "Bottom Layer" at 9020.49,6727.5 h60
  text "Copper" at 9950.23,6727.5 h60
  text "1.40mil" at 10810,6727.5 h60
  text "10" at 8610.58,6607.5 h60
  text "Bottom Solder" at 9020.49,6607.5 h60
  text "Solder Resist" at 9950.23,6607.5 h60
  text "0.40mil" at 10810,6607.5 h60
  text "3.5" at 11459.84,6607.5 h60
  text "11" at 8610.58,6487.5 h60
  text "Bottom Overlay" at 9020.49,6487.5 h60
  text ".Layer_Name" at 577,-858.49 h60
M13 Component Bodies Top:
  text ".Layer_Name" at 577,-858.49 h60
M14 Component Bodies Bottom:
  text ".Layer_Name" at 577,-858.49 h60
M15 Courtyards Top:
  text ".Layer_Name" at 577,-858.49 h60
M16 Courtyards Bottom:
  text ".Layer_Name" at 577,-858.49 h60
Drill Drawing:
  drawing of 192 lines, arcs and shapes, not listed
  text "Symbol" at 5360.6,3368.27 h72
  text "Quantity" at 5661.05,3368.27 h72
  text "Finished Hole Size" at 5992.86,3368.27 h72
  text "Plated" at 6628.96,3368.27 h72
  text "Hole Type" at 6887.96,3368.27 h72
  text "Drill Layer Pair" at 7262.94,3368.27 h72
  text "Hole Tolerance" at 7987.16,3368.27 h72
  text "2" at 5661.05,3243.94 h60
  text "126.58mil (3.215mm)" at 5992.86,3243.94 h60
  text "NPTH" at 6628.96,3243.94 h60
  text "Round" at 6887.96,3243.94 h60
  text "Top Layer - Bottom Layer" at 7262.94,3243.94 h60
  text "5" at 5661.05,3119.6 h60
  text "7.87mil (0.200mm)" at 5992.86,3119.6 h60
  text "PTH" at 6628.96,3119.6 h60
  text "Round" at 6887.96,3119.6 h60
  text "Top Layer - Bottom Layer" at 7262.94,3119.6 h60
  text "338" at 5661.05,2995.27 h60
  text "12.00mil (0.305mm)" at 5992.86,2995.27 h60
  text "PTH" at 6628.96,2995.27 h60
  text "Round" at 6887.96,2995.27 h60
  text "Top Layer - Bottom Layer" at 7262.94,2995.27 h60
  text "8" at 5661.05,2870.93 h60
  text "35.04mil (0.890mm)" at 5992.86,2870.93 h60
  text "PTH" at 6628.96,2870.93 h60
  text "Round" at 6887.96,2870.93 h60
  text "Top Layer - Bottom Layer" at 7262.94,2870.93 h60
  text "+/-3.15mil" at 7987.16,2870.93 h60
  text "26" at 5661.05,2746.6 h60
  text "39.37mil (1.000mm)" at 5992.86,2746.6 h60
  text "PTH" at 6628.96,2746.6 h60
  text "Round" at 6887.96,2746.6 h60
  text "Top Layer - Bottom Layer" at 7262.94,2746.6 h60
  text "33" at 5661.05,2622.26 h60
  text "40.00mil (1.016mm)" at 5992.86,2622.26 h60
  text "PTH" at 6628.96,2622.26 h60
  text "Round" at 6887.96,2622.26 h60
  text "Top Layer - Bottom Layer" at 7262.94,2622.26 h60
  text "1" at 5661.05,2497.93 h60
  text "59.06mil (1.500mm)" at 5992.86,2497.93 h60
  text "PTH" at 6628.96,2497.93 h60
  text "Round" at 6887.96,2497.93 h60
  text "Top Layer - Bottom Layer" at 7262.94,2497.93 h60
  text "+3.94mil/-0.00mil" at 7987.16,2497.93 h60
  text "1" at 5661.05,2373.59 h60
  text "59.06mil (1.500mm)" at 5992.86,2373.59 h60
  text "PTH" at 6628.96,2373.59 h60
  text "Round" at 6887.96,2373.59 h60
  text "Top Layer - Bottom Layer" at 7262.94,2373.59 h60
  text "2" at 5661.05,2249.26 h60
  text "61.81mil (1.570mm)" at 5992.86,2249.26 h60
  text "PTH" at 6628.96,2249.26 h60
  text "Round" at 6887.96,2249.26 h60
  text "Top Layer - Bottom Layer" at 7262.94,2249.26 h60
  text "+/-3.15mil" at 7987.16,2249.26 h60
  text "4" at 5661.05,2124.92 h60
  text "62.99mil (1.600mm)" at 5992.86,2124.92 h60
  text "PTH" at 6628.96,2124.92 h60
  text "Round" at 6887.96,2124.92 h60
  text "Top Layer - Bottom Layer" at 7262.94,2124.92 h60
  text "4" at 5661.05,2000.59 h60
  text "62.99mil (1.600mm)" at 5992.86,2000.59 h60
  text "PTH" at 6628.96,2000.59 h60
  text "Round" at 6887.96,2000.59 h60
  text "Top Layer - Bottom Layer" at 7262.94,2000.59 h60
  text "+3.94mil/-0.00mil" at 7987.16,2000.59 h60
  text "2" at 5661.05,1876.25 h60
  text "98.43mil (2.500mm)" at 5992.86,1876.25 h60
  text "PTH" at 6628.96,1876.25 h60
  text "Round" at 6887.96,1876.25 h60
  text "Top Layer - Bottom Layer" at 7262.94,1876.25 h60
  text "4" at 5661.05,1751.91 h60
  text "125.98mil (3.200mm)" at 5992.86,1751.91 h60
  text "PTH" at 6628.96,1751.91 h60
  text "Round" at 6887.96,1751.91 h60
  text "Top Layer - Bottom Layer" at 7262.94,1751.91 h60
  text "2" at 5661.05,1627.58 h60
  text "23.62mil (0.600mm)" at 5992.86,1627.58 h60
  text "PTH" at 6628.96,1627.58 h60
  text "Slot" at 6887.96,1627.58 h60
  text "Top Layer - Bottom Layer" at 7262.94,1627.58 h60
  text "2" at 5661.05,1503.24 h60
  text "27.56mil (0.700mm)" at 5992.86,1503.24 h60
  text "PTH" at 6628.96,1503.24 h60
  text "Slot" at 6887.96,1503.24 h60
  text "Top Layer - Bottom Layer" at 7262.94,1503.24 h60
  text "434 Total" at 5661.05,1378.91 h60
  text "Slot definitions :" at 5360.6,1291.88 h60
  text "Routed Path Length" at 5811.08,1291.88 h60
  text "= Calculated from tool start centre position to tool end centre position." at 6350.63,1291.88 h60
  text "Hole Length" at 5811.08,1242.14 h60
  text "= Routed Path Length + Tool Size = Slot length as defined in the PCB layout" at 6150.89,1242.14 h60
  text ".Layer_Name" at 577,-858.49 h60
M17 Embedded Cavity:
  text ".Layer_Name" at 577,-858.49 h60
M18 Embedded Assembly:
  text ".Layer_Name" at 577,-858.49 h60
M19 Embedded Keepout:
  text ".Layer_Name" at 577,-858.49 h60

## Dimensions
0,-400 to 1000,-400 on M2 Board Dimensions
0,0 to 3350,2200 on M2 Board Dimensions
0,0 to 3400,50 on M2 Board Dimensions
